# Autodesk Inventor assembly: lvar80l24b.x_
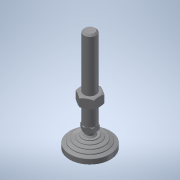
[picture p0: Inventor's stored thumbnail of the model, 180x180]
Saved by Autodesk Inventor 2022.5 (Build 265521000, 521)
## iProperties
Part Number: lvar80l24b.x_
Material: 一般
Document SubType Name: Assembly
Designer: ImaoCorp
Sending System: SOLIDWORKS 2017-2017317
MC: AMD64
MC_MODEL: Intel64 Family 6 Model 60 Stepping 3, GenuineIntel
OS: Windows_NT
FRU: Parasolid Version 29.0, build 201,  4-17-2017
FORMAT: text
GUISE: transmit
KEY: lvar80l24b
FILE: lvar80l24b.x_t
DATE: Mon Jul 01 18:15:16 2019
Author: ImaoCorp
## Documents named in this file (3)
- X:\14_SW2022-Inv2022\00_全2023-1023新製品(TCC)まで\l\lvar80l24b\LVAR80L24B.iam
- X:\14_SW2022-Inv2022\00_全2023-1023新製品(TCC)まで\l\lvar80l24b\lvar80l24b_01.ipt
- X:\14_SW2022-Inv2022\00_全2023-1023新製品(TCC)まで\l\lvar80l24b\lvar80l24b_02.ipt
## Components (2 placed, 2 different names)
1. lvar80l24b_01
2. lvar80l24b_02
